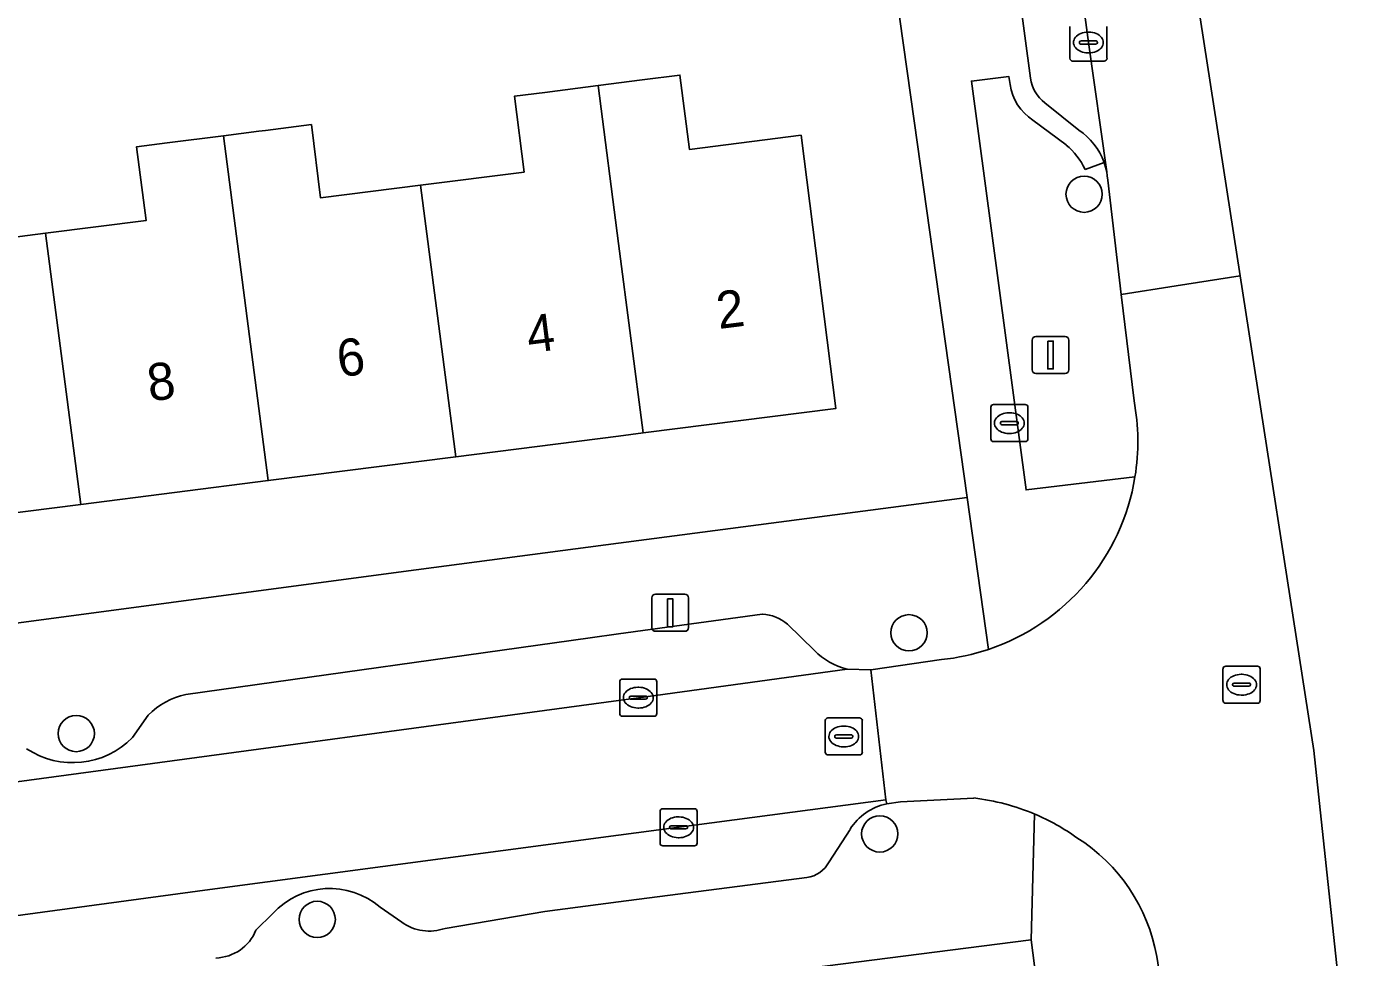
# Model space of a CAD drawing. Extents: x 163147 to 163550, y 380933 to 381639.
# Drawn here: x 163484.06 to 163519.95, y 381091.67 to 381116.74 of the extents above; entities that cross this region are included whole.
import ezdxf

# ---------------------------------------------------------------- set-up
doc = ezdxf.new("R2010")
doc.units = 0
for name, color, linetype in [('IMGEO_Boom', 7, 'Continuous'), ('IMGEO_Brandkraan', 7, 'Continuous'), ('IMGEO_Erf', 7, 'Continuous'), ('IMGEO_Groenvoorziening', 7, 'Continuous'), ('IMGEO_Kolk', 7, 'Continuous'), ('IMGEO_Lichtmast', 7, 'Continuous'), ('IMGEO_Muur', 7, 'Continuous'), ('IMGEO_Pand', 7, 'Continuous'), ('IMGEO_Pand_nummerreeks', 7, 'Continuous'), ('IMGEO_Parkeervlak_open', 7, 'Continuous'), ('IMGEO_Rijbaan_lokaal_open', 7, 'Continuous'), ('IMGEO_Rioolput', 7, 'Continuous'), ('IMGEO_Voetpad_open', 7, 'Continuous')]:
    doc.layers.add(name, color=color, linetype=linetype)

msp = doc.modelspace()

# ---------------------------------------------------------------- linework, layer by layer
at = {"layer": 'IMGEO_Boom'}
for centre in [(163512.541, 381112.224), (163507.823, 381100.408), (163485.391, 381097.695), (163507.035, 381094.991), (163491.882, 381092.687)]:
    msp.add_circle(centre, 0.489, dxfattribs=at)
at = {"layer": 'IMGEO_Brandkraan'}
for p, q in [((163510.025, 381105.632), (163510.025, 381106.484)), ((163510.1, 381106.558), (163510.952, 381106.558)), ((163511.026, 381106.484), (163511.026, 381105.632)), ((163510.284, 381106.052), (163510.284, 381106.064)), ((163510.722, 381106.015), (163510.324, 381106.015)), ((163510.327, 381106.101), (163510.725, 381106.101)), ((163510.513, 381106.338), (163510.538, 381106.338)), ((163510.768, 381106.064), (163510.768, 381106.052)), ((163510.536, 381105.778), (163510.511, 381105.778)), ((163510.952, 381105.558), (163510.1, 381105.558))]:
    msp.add_line(p, q, dxfattribs=at)
for points in [[(163510.025, 381105.632), (163510.025, 381106.484)], [(163510.1, 381106.558), (163510.952, 381106.558)], [(163511.026, 381106.484), (163511.026, 381105.632)], [(163510.952, 381105.558), (163510.1, 381105.558)]]:
    msp.add_lwpolyline(points, dxfattribs=at)
for centre, radius, start, end in [((163510.102, 381106.482), 0.0765, 91.552, 178.448), ((163510.102, 381106.482), 0.0765, 91.552, 178.448), ((163510.95, 381106.482), 0.0765, 1.552, 88.448), ((163510.95, 381106.482), 0.0765, 1.552, 88.448), ((163510.324, 381106.061), 0.0403, 85.8775, 175.7526), ((163510.321, 381106.051), 0.0366, 178.938, 274.7102), ((163510.725, 381106.058), 0.043, 264.8664, 352.4533), ((163510.729, 381106.063), 0.0386, 1.7309, 96.639), ((163510.102, 381105.634), 0.0765, 181.552, 268.448), ((163510.102, 381105.634), 0.0765, 181.552, 268.448), ((163510.95, 381105.634), 0.0765, 271.552, 358.448), ((163510.95, 381105.634), 0.0765, 271.552, 358.448)]:
    msp.add_arc(centre, radius, start, end, dxfattribs=at)
for centre, major_axis, ratio, start_param, end_param in [((163510.512, 381106.058), (-0.387, 0.002), 0.722429, 4.712389, 7.853982), ((163510.537, 381106.058), (-0.39, 0.002), 0.717154, 1.570796, 4.712389)]:
    msp.add_ellipse(centre, major_axis=major_axis, ratio=ratio, start_param=start_param, end_param=end_param, dxfattribs=at)
at = {"layer": 'IMGEO_Erf'}
for points in [[(163475.554, 381099.568), (163494.208, 381102.063), (163500, 381102.823), (163509.388, 381104.055), (163507.962, 381114.2), (163506.904, 381121.729), (163506.464, 381125), (163506.428, 381125.265), (163503.195, 381124.83), (163501.283, 381124.587), (163501.651, 381121.694), (163498.649, 381121.312), (163494.94, 381120.84), (163494.565, 381123.732), (163493.225, 381123.562), (163491.927, 381123.397), (163492.302, 381120.505), (163488.551, 381120.028), (163484.81, 381119.552), (163484.433, 381122.444), (163483.126, 381122.277)], [(163481.65, 381110.799), (163484.568, 381111.17), (163487.271, 381111.514), (163487.019, 381113.503), (163487.837, 381113.606), (163489.359, 381113.799), (163490.309, 381113.92), (163490.492, 381113.943), (163491.725, 381114.099), (163491.975, 381112.123), (163494.664, 381112.465), (163497.454, 381112.819), (163497.194, 381114.863), (163498.01, 381114.967), (163499.448, 381115.15), (163500.64, 381115.302), (163501.654, 381115.431), (163501.908, 381113.431), (163504.915, 381113.813), (163505.851, 381106.45), (163500.662, 381105.791), (163500, 381105.707), (163495.613, 381105.149), (163490.564, 381104.507), (163485.516, 381103.866), (163480.467, 381103.224)], [(163511.896, 381086.04), (163511.11, 381092.135), (163500, 381090.719)]]:
    msp.add_lwpolyline(points, dxfattribs=at)
at = {"layer": 'IMGEO_Groenvoorziening'}
for points in [[(163510.548, 381115.183), (163510.515, 381115.391), (163509.505, 381115.269), (163510.975, 381104.257), (163513.91, 381104.608)], [(163512.055, 381113.549), (163511.162, 381114.222)], [(163513.078, 381113.079), (163512.567, 381112.89)], [(163513.181, 381112.606), (163513.165, 381112.719), (163513.15, 381112.822)], [(163513.886, 381106.654), (163513.54, 381109.521), (163513.181, 381112.606)]]:
    msp.add_lwpolyline(points, dxfattribs=at)
for centre, radius, start, end in [((163511.885, 381115.36), 1.348, 187.5609, 237.5896), ((163510.849, 381112.084), 1.897, 25.1403, 50.5495), ((163511.474, 381112.491), 1.709, 11.171, 20.13), ((163508.063, 381105.563), 5.924, 350.7278, 10.6163)]:
    msp.add_arc(centre, radius, start, end, dxfattribs=at)
at = {"layer": 'IMGEO_Kolk'}
for p, q in [((163512.155, 381115.885), (163512.155, 381116.737)), ((163512.643, 381116.591), (163512.668, 381116.591)), ((163513.156, 381116.737), (163513.156, 381115.885)), ((163512.414, 381116.305), (163512.414, 381116.317)), ((163512.852, 381116.268), (163512.454, 381116.268)), ((163512.457, 381116.354), (163512.855, 381116.354)), ((163512.898, 381116.317), (163512.898, 381116.305)), ((163513.082, 381115.811), (163512.23, 381115.811)), ((163512.666, 381116.031), (163512.641, 381116.031)), ((163500.031, 381098.235), (163500.031, 381099.087)), ((163500.106, 381099.161), (163500.958, 381099.161)), ((163500.519, 381098.941), (163500.544, 381098.941)), ((163501.032, 381099.087), (163501.032, 381098.235)), ((163500.29, 381098.655), (163500.29, 381098.667)), ((163500.728, 381098.618), (163500.33, 381098.618)), ((163500.333, 381098.704), (163500.731, 381098.704)), ((163500.774, 381098.667), (163500.774, 381098.655)), ((163500.958, 381098.161), (163500.106, 381098.161)), ((163500.542, 381098.381), (163500.517, 381098.381)), ((163501.117, 381094.743), (163501.117, 381095.595)), ((163501.192, 381095.669), (163502.044, 381095.669)), ((163502.118, 381095.595), (163502.118, 381094.743)), ((163501.605, 381095.449), (163501.63, 381095.449)), ((163501.376, 381095.163), (163501.376, 381095.175)), ((163501.814, 381095.126), (163501.416, 381095.126)), ((163501.419, 381095.212), (163501.817, 381095.212)), ((163501.628, 381094.889), (163501.603, 381094.889)), ((163501.86, 381095.175), (163501.86, 381095.163)), ((163502.044, 381094.669), (163501.192, 381094.669))]:
    msp.add_line(p, q, dxfattribs=at)
for points in [[(163512.155, 381115.885), (163512.155, 381116.737)], [(163513.156, 381116.737), (163513.156, 381115.885)], [(163513.082, 381115.811), (163512.23, 381115.811)], [(163500.031, 381098.235), (163500.031, 381099.087)], [(163500.106, 381099.161), (163500.958, 381099.161)], [(163501.032, 381099.087), (163501.032, 381098.235)], [(163500.958, 381098.161), (163500.106, 381098.161)], [(163501.117, 381094.743), (163501.117, 381095.595)], [(163501.192, 381095.669), (163502.044, 381095.669)], [(163502.118, 381095.595), (163502.118, 381094.743)], [(163502.044, 381094.669), (163501.192, 381094.669)]]:
    msp.add_lwpolyline(points, dxfattribs=at)
for centre, radius, start, end in [((163512.454, 381116.314), 0.0403, 85.8775, 175.7526), ((163512.451, 381116.304), 0.0366, 178.938, 274.7102), ((163512.855, 381116.311), 0.043, 264.8664, 352.4533), ((163512.859, 381116.316), 0.0386, 1.7309, 96.639), ((163512.232, 381115.887), 0.0765, 181.552, 268.448), ((163512.232, 381115.887), 0.0765, 181.552, 268.448), ((163513.08, 381115.887), 0.0765, 271.552, 358.448), ((163513.08, 381115.887), 0.0765, 271.552, 358.448), ((163500.108, 381099.085), 0.0765, 91.552, 178.448), ((163500.108, 381099.085), 0.0765, 91.552, 178.448), ((163500.956, 381099.085), 0.0765, 1.552, 88.448), ((163500.956, 381099.085), 0.0765, 1.552, 88.448), ((163500.33, 381098.664), 0.0403, 85.8775, 175.7526), ((163500.327, 381098.654), 0.0366, 178.938, 274.7102), ((163500.731, 381098.661), 0.043, 264.8664, 352.4533), ((163500.735, 381098.666), 0.0386, 1.7309, 96.639), ((163500.108, 381098.237), 0.0765, 181.552, 268.448), ((163500.108, 381098.237), 0.0765, 181.552, 268.448), ((163500.956, 381098.237), 0.0765, 271.552, 358.448), ((163500.956, 381098.237), 0.0765, 271.552, 358.448), ((163501.194, 381095.593), 0.0765, 91.552, 178.448), ((163501.194, 381095.593), 0.0765, 91.552, 178.448), ((163502.042, 381095.593), 0.0765, 1.552, 88.448), ((163502.042, 381095.593), 0.0765, 1.552, 88.448), ((163501.416, 381095.172), 0.0403, 85.8775, 175.7526), ((163501.413, 381095.162), 0.0366, 178.938, 274.7102), ((163501.817, 381095.169), 0.043, 264.8664, 352.4533), ((163501.821, 381095.174), 0.0386, 1.7309, 96.639), ((163501.194, 381094.745), 0.0765, 181.552, 268.448), ((163501.194, 381094.745), 0.0765, 181.552, 268.448), ((163502.042, 381094.745), 0.0765, 271.552, 358.448), ((163502.042, 381094.745), 0.0765, 271.552, 358.448)]:
    msp.add_arc(centre, radius, start, end, dxfattribs=at)
for centre, major_axis, ratio, start_param, end_param in [((163512.642, 381116.311), (-0.387, 0.002), 0.722429, 4.712389, 7.853982), ((163512.667, 381116.311), (-0.39, 0.002), 0.717154, 1.570796, 4.712389), ((163500.518, 381098.661), (-0.387, 0.002), 0.722429, 4.712389, 7.853982), ((163500.543, 381098.661), (-0.39, 0.002), 0.717154, 1.570796, 4.712389), ((163501.604, 381095.169), (-0.387, 0.002), 0.722429, 4.712389, 7.853982), ((163501.629, 381095.169), (-0.39, 0.002), 0.717154, 1.570796, 4.712389)]:
    msp.add_ellipse(centre, major_axis=major_axis, ratio=ratio, start_param=start_param, end_param=end_param, dxfattribs=at)
at = {"layer": 'IMGEO_Lichtmast'}
for p, q in [((163511.139, 381107.492), (163511.139, 381108.292)), ((163511.139, 381108.292), (163511.139, 381107.492)), ((163511.239, 381108.392), (163512.029, 381108.392)), ((163512.029, 381108.392), (163511.239, 381108.392)), ((163512.129, 381108.292), (163512.129, 381107.492)), ((163512.129, 381107.492), (163512.129, 381108.292)), ((163512.029, 381107.392), (163511.239, 381107.392)), ((163511.239, 381107.392), (163512.029, 381107.392)), ((163500.896, 381100.548), (163500.896, 381101.348)), ((163500.896, 381101.348), (163500.896, 381100.548)), ((163500.996, 381101.448), (163501.786, 381101.448)), ((163501.786, 381101.448), (163500.996, 381101.448)), ((163501.886, 381101.348), (163501.886, 381100.548)), ((163501.886, 381100.548), (163501.886, 381101.348)), ((163501.786, 381100.448), (163500.996, 381100.448)), ((163500.996, 381100.448), (163501.786, 381100.448))]:
    msp.add_line(p, q, dxfattribs=at)
for points in [[(163511.559, 381108.267), (163511.709, 381108.267), (163511.709, 381107.517), (163511.559, 381107.517), (163511.559, 381108.267)], [(163501.316, 381101.323), (163501.466, 381101.323), (163501.466, 381100.573), (163501.316, 381100.573), (163501.316, 381101.323)]]:
    msp.add_lwpolyline(points, dxfattribs=at)
for centre, start, end in [((163511.239, 381108.292), 90, 180), ((163511.239, 381108.292), 90, 180), ((163512.029, 381108.292), 0, 90), ((163512.029, 381108.292), 360, 90), ((163511.239, 381107.492), 180, 270), ((163511.239, 381107.492), 180, 270), ((163512.029, 381107.492), 270, 0), ((163512.029, 381107.492), 270, 0), ((163500.996, 381101.348), 90, 180), ((163500.996, 381101.348), 90, 180), ((163501.786, 381101.348), 0, 90), ((163501.786, 381101.348), 360, 90), ((163500.996, 381100.548), 180, 270), ((163500.996, 381100.548), 180, 270), ((163501.786, 381100.548), 270, 0), ((163501.786, 381100.548), 270, 0)]:
    msp.add_arc(centre, 0.1, start, end, dxfattribs=at)
at = {"layer": 'IMGEO_Muur'}
msp.add_lwpolyline([(163507.962, 381114.2), (163506.904, 381121.729)], dxfattribs=at)
at = {"layer": 'IMGEO_Pand'}
for points in [[(163499.448, 381115.15), (163500, 381110.895), (163500.662, 381105.791), (163505.851, 381106.45), (163504.915, 381113.813), (163501.908, 381113.431), (163501.654, 381115.431), (163500.64, 381115.302)], [(163499.448, 381115.15), (163498.01, 381114.967), (163497.194, 381114.863), (163497.454, 381112.819), (163494.664, 381112.465), (163495.613, 381105.149), (163500, 381105.707), (163500.662, 381105.791), (163500, 381110.895)], [(163494.664, 381112.465), (163491.975, 381112.123), (163491.725, 381114.099), (163490.492, 381113.943), (163490.309, 381113.92), (163489.359, 381113.799), (163490.564, 381104.507), (163495.613, 381105.149)], [(163489.359, 381113.799), (163487.837, 381113.606), (163487.019, 381113.503), (163487.271, 381111.514), (163484.568, 381111.17), (163485.516, 381103.866), (163490.564, 381104.507)], [(163484.568, 381111.17), (163481.65, 381110.799), (163481.398, 381112.79), (163480.377, 381112.661), (163479.261, 381112.519), (163480.467, 381103.224), (163485.516, 381103.866)]]:
    msp.add_lwpolyline(points, close=True, dxfattribs=at)
at = {"layer": 'IMGEO_Parkeervlak_open'}
for points in [[(163502.646, 381178.504), (163511.092, 381115.35)], [(163513.15, 381112.822), (163512.657, 381116.312), (163510.084, 381135.559), (163507.418, 381155.47)], [(163511.483, 381114.685), (163512.396, 381113.951)], [(163503.872, 381100.906), (163500, 381100.378), (163499.234, 381100.274), (163488.345, 381098.744)], [(163505.274, 381099.936), (163504.55, 381100.637)], [(163470.232, 381094.562), (163500, 381098.587), (163500.533, 381098.659), (163506.154, 381099.43)], [(163487.333, 381098.187), (163486.905, 381097.584)], [(163507.229, 381095.804), (163507.201, 381095.911), (163500, 381094.955), (163488.993, 381093.493), (163470.891, 381091.039)], [(163505.67, 381094.24), (163506.235, 381095.114)], [(163495.325, 381092.446), (163498.014, 381092.902), (163500, 381093.16), (163505.069, 381093.817)], [(163490.232, 381092.394), (163490.683, 381092.844)], [(163493.581, 381093.017), (163494.159, 381092.615)]]:
    msp.add_lwpolyline(points, dxfattribs=at)
for centre, radius, start, end in [((163512.099, 381115.494), 1.017, 188.1677, 232.7408), ((163511.392, 381112.463), 1.795, 20.0704, 55.9883), ((163511.474, 381112.491), 1.709, 11.171, 20.13), ((163503.841, 381099.838), 1.069, 48.405, 88.3131), ((163506.581, 381101.19), 1.811, 223.8292, 256.373), ((163488.716, 381096.872), 1.908, 101.2105, 136.4459), ((163485.298, 381099.164), 2.254, 236.5453, 315.4769), ((163507.562, 381094.263), 1.577, 102.207, 147.327), ((163504.98, 381094.582), 0.77, 276.6312, 333.6466), ((163492.221, 381091.437), 2.084, 49.2762, 137.5564), ((163489.116, 381092.855), 1.208, 271.8158, 337.5524), ((163494.901, 381093.626), 1.254, 233.7291, 289.7769)]:
    msp.add_arc(centre, radius, start, end, dxfattribs=at)
at = {"layer": 'IMGEO_Rijbaan_lokaal_open'}
for points in [[(163514.8, 381126.75), (163514.789, 381126.831), (163513.587, 381135.867), (163510.87, 381156.109), (163507.648, 381179.955), (163504.184, 381179.487), (163504.439, 381177.585), (163507.418, 381155.47), (163510.084, 381135.559), (163512.657, 381116.312), (163513.15, 381112.822), (163513.165, 381112.719), (163513.181, 381112.606), (163513.54, 381109.521), (163515.019, 381109.754), (163516.743, 381110.026), (163514.166, 381126.655)], [(163500, 381094.955), (163507.201, 381095.911), (163506.797, 381099.412), (163506.154, 381099.43), (163500.533, 381098.659), (163500, 381098.587), (163470.232, 381094.562), (163465.682, 381093.963), (163465.527, 381093.942), (163453.767, 381092.507), (163454.236, 381088.812), (163463.604, 381090.087), (163468.211, 381090.689), (163470.891, 381091.039), (163488.993, 381093.493)]]:
    msp.add_lwpolyline(points, close=True, dxfattribs=at)
for points in [[(163519.851, 381086.738), (163518.724, 381097.242), (163516.743, 381110.026), (163515.019, 381109.754), (163513.54, 381109.521), (163513.886, 381106.654)], [(163508.7, 381099.686), (163506.797, 381099.412), (163507.201, 381095.911), (163507.229, 381095.804), (163507.597, 381095.857), (163509.571, 381095.958)], [(163514.495, 381091.686), (163515.38, 381086.08), (163517.56, 381086.401), (163519.851, 381086.738)]]:
    msp.add_lwpolyline(points, dxfattribs=at)
for centre, radius, start, end in [((163508.063, 381105.563), 5.924, 350.7278, 10.6163), ((163508.081, 381105.56), 5.906, 288.5809, 350.7201), ((163508.089, 381105.509), 5.855, 275.9879, 288.6659), ((163508.867, 381089.998), 6.002, 67.0406, 83.2622), ((163508.903, 381090.065), 5.926, 54.4615, 67.1052), ((163509.81, 381090.864), 4.756, 9.9561, 57.7703)]:
    msp.add_arc(centre, radius, start, end, dxfattribs=at)
at = {"layer": 'IMGEO_Rioolput'}
for p, q in [((163516.281, 381098.584), (163516.281, 381099.436)), ((163516.356, 381099.51), (163517.208, 381099.51)), ((163516.769, 381099.29), (163516.794, 381099.29)), ((163517.282, 381099.436), (163517.282, 381098.584)), ((163516.54, 381099.004), (163516.54, 381099.016)), ((163516.978, 381098.967), (163516.58, 381098.967)), ((163516.583, 381099.053), (163516.981, 381099.053)), ((163517.024, 381099.016), (163517.024, 381099.004)), ((163517.208, 381098.51), (163516.356, 381098.51)), ((163516.792, 381098.73), (163516.767, 381098.73)), ((163505.64, 381098.117), (163506.492, 381098.117)), ((163505.565, 381097.191), (163505.565, 381098.043)), ((163506.053, 381097.897), (163506.078, 381097.897)), ((163506.566, 381098.043), (163506.566, 381097.191)), ((163505.824, 381097.611), (163505.824, 381097.623)), ((163506.262, 381097.574), (163505.864, 381097.574)), ((163505.867, 381097.66), (163506.265, 381097.66)), ((163506.308, 381097.623), (163506.308, 381097.611)), ((163506.492, 381097.117), (163505.64, 381097.117)), ((163506.076, 381097.337), (163506.051, 381097.337))]:
    msp.add_line(p, q, dxfattribs=at)
for points in [[(163516.281, 381098.584), (163516.281, 381099.436)], [(163516.356, 381099.51), (163517.208, 381099.51)], [(163517.282, 381099.436), (163517.282, 381098.584)], [(163517.208, 381098.51), (163516.356, 381098.51)], [(163505.64, 381098.117), (163506.492, 381098.117)], [(163505.565, 381097.191), (163505.565, 381098.043)], [(163506.566, 381098.043), (163506.566, 381097.191)], [(163506.492, 381097.117), (163505.64, 381097.117)]]:
    msp.add_lwpolyline(points, dxfattribs=at)
for centre, radius, start, end in [((163516.358, 381099.434), 0.0765, 91.552, 178.448), ((163516.358, 381099.434), 0.0765, 91.552, 178.448), ((163517.206, 381099.434), 0.0765, 1.552, 88.448), ((163517.206, 381099.434), 0.0765, 1.552, 88.448), ((163516.58, 381099.013), 0.0403, 85.8775, 175.7526), ((163516.577, 381099.003), 0.0366, 178.938, 274.7102), ((163516.981, 381099.01), 0.043, 264.8664, 352.4533), ((163516.985, 381099.015), 0.0386, 1.7309, 96.639), ((163516.358, 381098.586), 0.0765, 181.552, 268.448), ((163516.358, 381098.586), 0.0765, 181.552, 268.448), ((163517.206, 381098.586), 0.0765, 271.552, 358.448), ((163517.206, 381098.586), 0.0765, 271.552, 358.448), ((163505.642, 381098.041), 0.0765, 91.552, 178.448), ((163505.642, 381098.041), 0.0765, 91.552, 178.448), ((163506.49, 381098.041), 0.0765, 1.552, 88.448), ((163506.49, 381098.041), 0.0765, 1.552, 88.448), ((163505.864, 381097.62), 0.0403, 85.8775, 175.7526), ((163505.861, 381097.61), 0.0366, 178.938, 274.7102), ((163506.265, 381097.617), 0.043, 264.8664, 352.4533), ((163506.269, 381097.622), 0.0386, 1.7309, 96.639), ((163505.642, 381097.193), 0.0765, 181.552, 268.448), ((163505.642, 381097.193), 0.0765, 181.552, 268.448), ((163506.49, 381097.193), 0.0765, 271.552, 358.448), ((163506.49, 381097.193), 0.0765, 271.552, 358.448)]:
    msp.add_arc(centre, radius, start, end, dxfattribs=at)
for centre, major_axis, ratio, start_param, end_param in [((163516.768, 381099.01), (-0.387, 0.002), 0.722429, 4.712389, 7.853982), ((163516.793, 381099.01), (-0.39, 0.002), 0.717154, 1.570796, 4.712389), ((163506.052, 381097.617), (-0.387, 0.002), 0.722429, 4.712389, 7.853982), ((163506.077, 381097.617), (-0.39, 0.002), 0.717154, 1.570796, 4.712389)]:
    msp.add_ellipse(centre, major_axis=major_axis, ratio=ratio, start_param=start_param, end_param=end_param, dxfattribs=at)
at = {"layer": 'IMGEO_Voetpad_open'}
for points in [[(163493.605, 381221.412), (163497.667, 381190.955), (163497.876, 381189.391), (163500, 381173.462), (163501.959, 381158.775), (163502.129, 381157.501), (163502.828, 381152.255), (163503.491, 381147.312), (163503.564, 381146.764), (163503.03, 381146.692), (163503.638, 381142.159), (163504.321, 381137.076), (163504.344, 381136.902), (163504.857, 381136.97), (163505.516, 381132.062), (163505.582, 381131.571), (163506.211, 381126.885), (163506.428, 381125.265), (163506.464, 381125), (163506.904, 381121.729), (163507.962, 381114.2), (163509.388, 381104.055), (163509.963, 381099.962)], [(163511.092, 381115.35), (163502.646, 381178.504)], [(163513.91, 381104.608), (163510.975, 381104.257), (163509.505, 381115.269), (163510.515, 381115.391), (163510.548, 381115.183)], [(163512.396, 381113.951), (163511.483, 381114.685)], [(163511.162, 381114.222), (163512.055, 381113.549)], [(163512.567, 381112.89), (163513.078, 381113.079)], [(163509.963, 381099.962), (163509.388, 381104.055), (163500, 381102.823), (163494.208, 381102.063), (163475.554, 381099.568), (163475.175, 381102.551), (163473.737, 381102.51), (163473.559, 381102.505), (163451.716, 381099.596), (163452.309, 381092.324), (163453.528, 381092.478)], [(163488.345, 381098.744), (163499.234, 381100.274), (163500, 381100.378), (163503.872, 381100.906)], [(163504.55, 381100.637), (163505.274, 381099.936)], [(163506.154, 381099.43), (163506.797, 381099.412), (163508.7, 381099.686)], [(163486.905, 381097.584), (163487.333, 381098.187)], [(163509.571, 381095.958), (163507.597, 381095.857), (163507.229, 381095.804)], [(163496.185, 381090.233), (163500, 381090.719), (163511.11, 381092.135), (163511.208, 381095.524)], [(163511.208, 381095.524), (163511.11, 381092.135), (163511.896, 381086.04)], [(163506.235, 381095.114), (163505.67, 381094.24)], [(163505.069, 381093.817), (163500, 381093.16), (163498.014, 381092.902), (163495.325, 381092.446)], [(163490.683, 381092.844), (163490.232, 381092.394)], [(163494.159, 381092.615), (163493.581, 381093.017)], [(163529.362, 380981.369), (163528.841, 380985.339), (163526.859, 381000), (163525.88, 381007.238), (163523.013, 381028.635), (163520.526, 381047.354), (163517.691, 381068.556), (163515.628, 381083.882), (163515.38, 381086.08), (163514.495, 381091.686)]]:
    msp.add_lwpolyline(points, dxfattribs=at)
for centre, radius, start, end in [((163512.099, 381115.494), 1.017, 188.1677, 232.7408), ((163511.885, 381115.36), 1.348, 187.5609, 237.5896), ((163511.392, 381112.463), 1.795, 20.0704, 55.9883), ((163510.849, 381112.084), 1.897, 25.1403, 50.5495), ((163508.081, 381105.56), 5.906, 288.5809, 350.7201), ((163503.841, 381099.838), 1.069, 48.405, 88.3131), ((163506.581, 381101.19), 1.811, 223.8292, 256.373), ((163508.089, 381105.509), 5.855, 275.9879, 288.6659), ((163488.716, 381096.872), 1.908, 101.2105, 136.4459), ((163485.298, 381099.164), 2.254, 236.5453, 315.4769), ((163508.867, 381089.998), 6.002, 67.0406, 83.2622), ((163507.562, 381094.263), 1.577, 102.207, 147.327), ((163508.903, 381090.065), 5.926, 54.4615, 67.1052), ((163509.81, 381090.864), 4.756, 9.9561, 57.7703), ((163504.98, 381094.582), 0.77, 276.6312, 333.6466), ((163492.221, 381091.437), 2.084, 49.2762, 137.5564), ((163489.116, 381092.855), 1.208, 271.8158, 337.5524), ((163494.901, 381093.626), 1.254, 233.7291, 289.7769)]:
    msp.add_arc(centre, radius, start, end, dxfattribs=at)

# ---------------------------------------------------------------- texts
at = {"layer": 'IMGEO_Pand_nummerreeks'}
for s, p in [('2', (163502.701, 381108.59)), ('4', (163497.59, 381107.941)), ('6', (163492.478, 381107.291)), ('8', (163487.369, 381106.641))]:
    msp.add_text(s, height=1, rotation=7.2422, dxfattribs=at).set_placement(p)

doc.saveas('drawing.dxf')
